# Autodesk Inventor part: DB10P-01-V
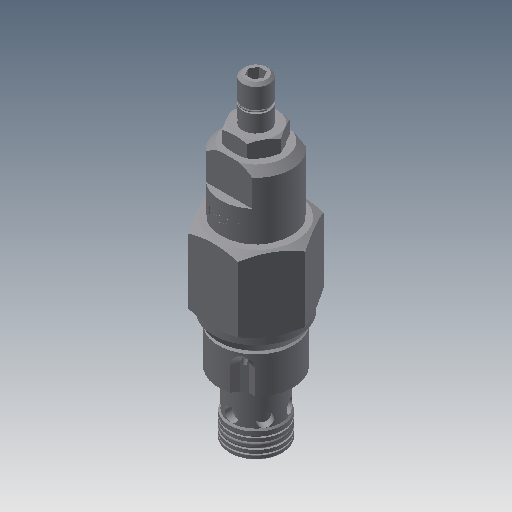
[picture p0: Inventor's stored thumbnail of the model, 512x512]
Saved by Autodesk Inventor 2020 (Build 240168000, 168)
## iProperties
Created: 2015-03
Part Number: DB10P-01-V
Material: Generico
Document SubType Name: Modeling
Designer: Carlo
Density: 1 g/cm^3
Appearance: Default
Title: DB10P-01-V.STEP
Description: STEP AP203
Creation Date: 2015-03-12
Sending System: SolidWorks 2014
Preprocessor: SwSTEP 2.0
DataBaseUnit: MM
Author: Carlo
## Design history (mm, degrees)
node "DB10P-01-V1"
node "Piano di lavoro1"
node "Piano di lavoro2"
node "Asse di lavoro1"
node "Imported1"
node "Base1"
other parameters: "d0" = 0, "d1" = 0
